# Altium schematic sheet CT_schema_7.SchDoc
size 287 x 160 mm
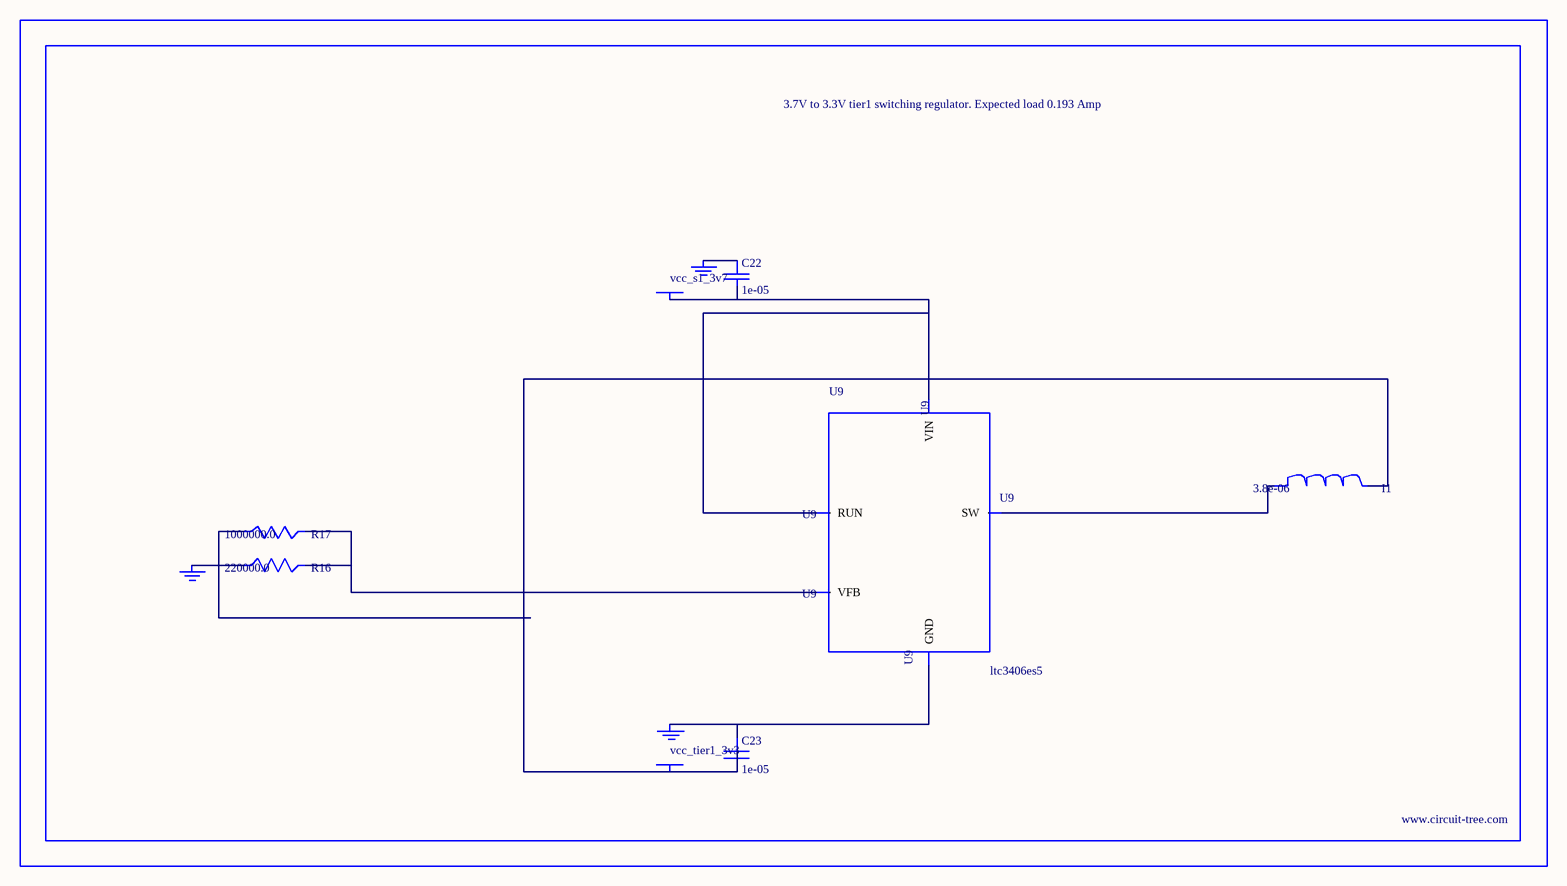
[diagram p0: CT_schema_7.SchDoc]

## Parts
BORDER6  (no value)
C22  1e-05  [C0805]
C23  1e-05  [C0805]
GND_INSTANCE_6_0  (no value)
GND_INSTANCE_6_1  (no value)
GND_INSTANCE_6_2  (no value)
I1  3.8e-06  [DR1040]
POWER_INSTANCE_6_0  vcc_tier1_3v3
POWER_INSTANCE_6_1  vcc_s1_3v7
R16  220000.0  [R0603]
R17  1000000.0  [R0603]
U9  ltc3406es5  [TSOT-23-5]

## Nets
NetC22_1: C22.1 GND_INSTANCE_6_1.0(GND)
NetC22_2: C22.2 POWER_INSTANCE_6_1.0(PWR) U9.1(RUN) U9.4(VIN)
NetC23_1: C23.1 GND_INSTANCE_6_0.0(GND) U9.2(GND)
NetC23_2: C23.2 I1.2 POWER_INSTANCE_6_0.0(PWR) R17.1
NetGND_INSTANCE_6_2_0: GND_INSTANCE_6_2.0(GND) R16.1
NetI1_1: I1.1 U9.3(SW)
NetR16_2: R16.2 R17.2 U9.5(VFB)

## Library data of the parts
BORDER6 = BORDER_PAGE6
C22 C23 = C0805C106K8RACTU
GND_INSTANCE_6_0-GND_INSTANCE_6_2 = GND
I1 = DR1040-3R8-R
POWER_INSTANCE_6_0 POWER_INSTANCE_6_1 = PWR
R16 = RC0603JR-07220KL
R17 = RC0603JR-071ML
